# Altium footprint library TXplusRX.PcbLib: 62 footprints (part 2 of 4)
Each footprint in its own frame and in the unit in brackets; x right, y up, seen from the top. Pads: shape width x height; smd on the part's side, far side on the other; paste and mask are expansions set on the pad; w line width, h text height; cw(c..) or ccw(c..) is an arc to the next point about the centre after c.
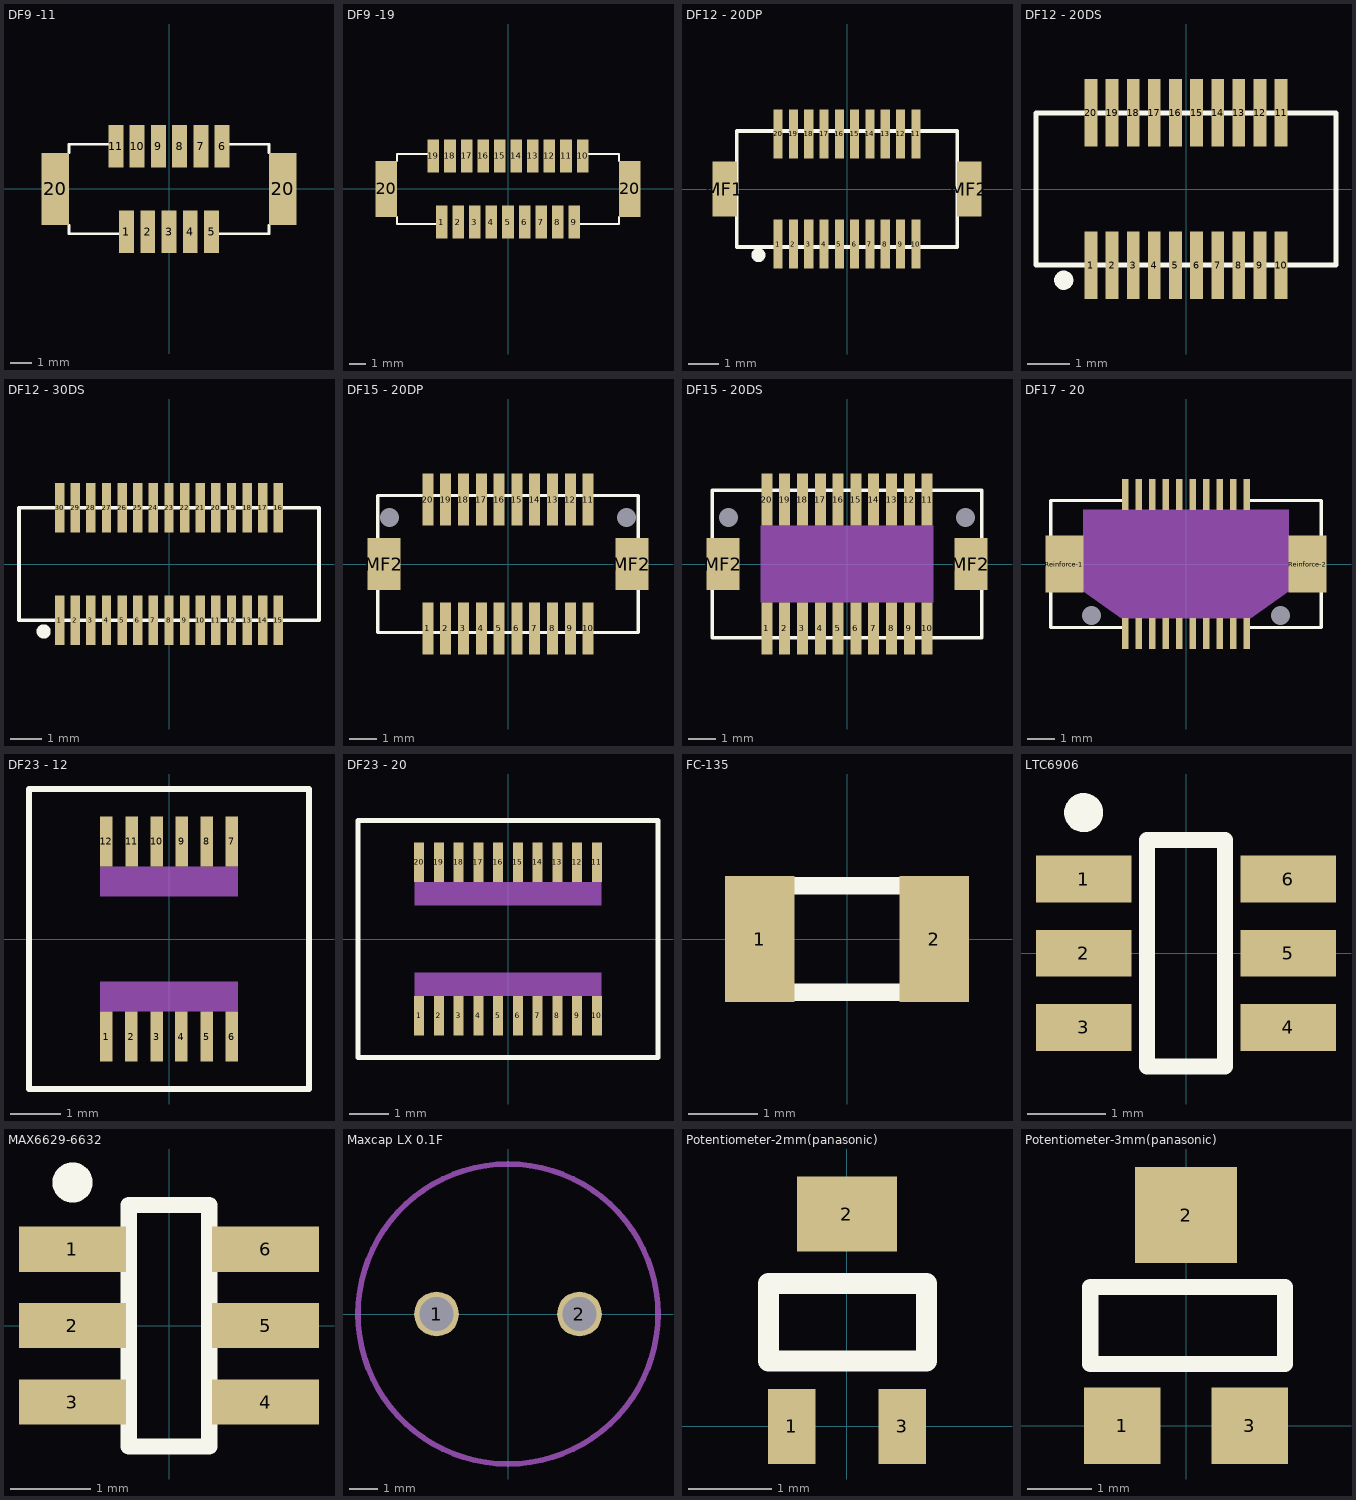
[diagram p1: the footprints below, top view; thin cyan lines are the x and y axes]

## DF9 -11 [mm] "DF9 -11, 11Pin Connector"
pads (13):
  rect 0.7x2 smd: 1(-2,-2) 2(-1,-2) 3(0,-2) 4(1,-2) 5(2,-2) 6(2.5,2) 7(1.5,2) 8(0.5,2) 9(-0.5,2) 10(-1.5,2) 11(-2.5,2)
  rect 1.3x3.4 smd: 20(-5.35,0) 20(5.35,0)
Top Overlay:
  lines w0.127: -4.7,-1.7 -4.7,-2.1 -2.3,-2.1 ; -4.7,1.7 -4.7,2.1 -2.8,2.1 ; 2.3,-2.1 4.7,-2.1 4.7,-1.7 ; 2.8,2.1 4.7,2.1 4.7,1.7

## DF9 -19 [mm] "DF9 -19, 19 Pin Connector"
pads (21):
  rect 0.7x2 smd: 1(-4,-2) 2(-3,-2) 3(-2,-2) 4(-1,-2) 5(0,-2) 6(1,-2) 7(2,-2) 8(3,-2) 9(4,-2) 10(4.5,2) 11(3.5,2) 12(2.5,2) 13(1.5,2) 14(0.5,2) 15(-0.5,2) 16(-1.5,2) 17(-2.5,2) 18(-3.5,2) 19(-4.5,2)
  rect 1.3x3.4 smd: 20(-7.35,0) 20(7.35,0)
Top Overlay:
  lines w0.127: -6.7,-1.7 -6.7,-2.1 -4.3,-2.1 ; -6.7,1.7 -6.7,2.1 -4.8,2.1 ; 4.3,-2.1 6.7,-2.1 6.7,-1.7 ; 4.8,2.1 6.7,2.1 6.7,1.7

## DF12 - 20DP [mm] "DF12 - 20DP, Connector Header"
height 2.3
pads (22):
  rect 0.3x1.6 smd: 1(-2.25,-1.8) 2(-1.75,-1.8) 3(-1.25,-1.8) 4(-0.75,-1.8) 5(-0.25,-1.8) 6(0.25,-1.8) 7(0.75,-1.8) 8(1.25,-1.8) 9(1.75,-1.8) 10(2.25,-1.8) 11(2.25,1.8) 12(1.75,1.8) 13(1.25,1.8) 14(0.75,1.8) 15(0.25,1.8) 16(-0.25,1.8) 17(-0.75,1.8) 18(-1.25,1.8) 19(-1.75,1.8) 20(-2.25,1.8)
  rect 0.8x1.8 smd: MF1(-4,0) MF2(4,0)
Top Overlay:
  circle w0.254: c-2.894,-2.159 r0.1
  lines w0.127: -3.6,-1.9 3.6,-1.9 3.6,1.9 -3.6,1.9 -3.6,-1.9
Mechanical 1:
  text "Conductors in area must be masked" at -2.1,0 h0.3
3D body: height 0, standoff 0, extent -2.4,-1 2.4,1

## DF12 - 20DS [mm] "DF12 - 20DS, Connector Receptacle"
height 2.7
pads (20):
  rect 0.3x1.6 smd: 1(-2.25,-1.8) 2(-1.75,-1.8) 3(-1.25,-1.8) 4(-0.75,-1.8) 5(-0.25,-1.8) 6(0.25,-1.8) 7(0.75,-1.8) 8(1.25,-1.8) 9(1.75,-1.8) 10(2.25,-1.8) 11(2.25,1.8) 12(1.75,1.8) 13(1.25,1.8) 14(0.75,1.8) 15(0.25,1.8) 16(-0.25,1.8) 17(-0.75,1.8) 18(-1.25,1.8) 19(-1.75,1.8) 20(-2.25,1.8)
Top Overlay:
  circle w0.254: c-2.894,-2.159 r0.1
  lines w0.127: -3.55,-1.8 3.55,-1.8 3.55,1.8 -3.55,1.8 -3.55,-1.8
Mechanical 1:
  text "Conductors in area must be masked" at -2.1,0 h0.3
3D body: height 0, standoff 0, extent -2.4,-1 2.4,1

## DF12 - 30DS [mm] "DF12 - 30DS, Connector Receptacle"
height 2.7
pads (30):
  rect 0.3x1.6 smd: 1(-3.5,-1.8) 2(-3,-1.8) 3(-2.5,-1.8) 4(-2,-1.8) 5(-1.5,-1.8) 6(-1,-1.8) 7(-0.5,-1.8) 8(0,-1.8) 9(0.5,-1.8) 10(1,-1.8) 11(1.5,-1.8) 12(2,-1.8) 13(2.5,-1.8) 14(3,-1.8) 15(3.5,-1.8) 16(3.5,1.8) 17(3,1.8) 18(2.5,1.8) 19(2,1.8) 20(1.5,1.8) 21(1,1.8) 22(0.5,1.8) 23(0,1.8) 24(-0.5,1.8) 25(-1,1.8) 26(-1.5,1.8) 27(-2,1.8) 28(-2.5,1.8) 29(-3,1.8) 30(-3.5,1.8)
Top Overlay:
  circle w0.254: c-4.012,-2.159 r0.1
  lines w0.127: -4.8,-1.8 4.8,-1.8 4.8,1.8 -4.8,1.8 -4.8,-1.8
Mechanical 1:
  text "Conductors in area must be masked" at -2.1,0 h0.3
3D body: height 0, standoff 0, extent -3.7,-1 3.7,1

## DF15 - 20DP [mm] "DF15 - 20DP, Connector Header"
height 3.2
pads (24):
  rect 0.4x1.9 smd: 1(-2.925,-2.35) 2(-2.275,-2.35) 3(-1.625,-2.35) 4(-0.975,-2.35) 5(-0.325,-2.35) 6(0.325,-2.35) 7(0.975,-2.35) 8(1.625,-2.35) 9(2.275,-2.35) 10(2.925,-2.35) 11(2.925,2.35) 12(2.275,2.35) 13(1.625,2.35) 14(0.975,2.35) 15(0.325,2.35) 16(-0.325,2.35) 17(-0.975,2.35) 18(-1.625,2.35) 19(-2.275,2.35) 20(-2.925,2.35)
  round 0 hole 0.7 unplated: 2(4.325,1.7) boss1(-4.325,1.7)
  rect 1.2x1.9 smd: MF2(-4.525,0) MF2(4.525,0)
Top Overlay:
  lines w0.127: -4.75,-2.5 4.75,-2.5 4.75,2.5 -4.75,2.5 -4.75,-2.5

## DF15 - 20DS [mm] "DF15 - 20DS, Connector Receptacle"
height 3.2
pads (24):
  rect 0.4x1.9 smd: 1(-2.925,-2.35) 2(-2.275,-2.35) 3(-1.625,-2.35) 4(-0.975,-2.35) 5(-0.325,-2.35) 6(0.325,-2.35) 7(0.975,-2.35) 8(1.625,-2.35) 9(2.275,-2.35) 10(2.925,-2.35) 11(2.925,2.35) 12(2.275,2.35) 13(1.625,2.35) 14(0.975,2.35) 15(0.325,2.35) 16(-0.325,2.35) 17(-0.975,2.35) 18(-1.625,2.35) 19(-2.275,2.35) 20(-2.925,2.35)
  round 0 hole 0.7 unplated: boss1(-4.325,1.7) boss2(4.325,1.7)
  rect 1.2x1.9 smd: MF2(-4.525,0) MF2(4.525,0)
Top Overlay:
  lines w0.127: -4.925,-2.7 4.925,-2.7 4.925,2.7 -4.925,2.7 -4.925,-2.7
Mechanical 1:
  rectangle: -3.163,-1.4 3.163,1.4
  text "Conductors in area must be masked" at -2.8,-1.9 h0.4

## DF17 - 20 [mm] "DF17 - 20, Connector"
pads (24):
  rect 0.25x1.15 smd: 1(-2.25,-2.575) 2(-1.75,-2.575) 3(-1.25,-2.575) 4(-0.75,-2.575) 5(-0.25,-2.575) 6(0.25,-2.575) 7(0.75,-2.575) 8(1.25,-2.575) 9(1.75,-2.575) 10(2.25,-2.575) 11(2.25,2.575) 12(1.75,2.575) 13(1.25,2.575) 14(0.75,2.575) 15(0.25,2.575) 16(-0.25,2.575) 17(-0.75,2.575) 18(-1.25,2.575) 19(-1.75,2.575) 20(-2.25,2.575)
  round 0 hole 0.7 unplated: Guide_Post-1(-3.5,-1.9) Guide_Post-2(3.5,-1.9)
  rect 1.4x2.1 smd: Reinforce-1(-4.5,0) Reinforce-2(4.5,0)
Top Overlay:
  lines w0.127: -5,-1.05 -5,-2.35 -2.35,-2.35 ; -5,1.05 -5,2.35 -2.35,2.35 ; 2.35,-2.35 5,-2.35 5,-1.05 ; 2.4,2.35 5,2.35 5,1.05
Mechanical 1:
  region: -3.8,2 -3.8,-1 -2.4,-2 2.4,-2 3.8,-1 3.8,2
  text "Conductors in area must be masked" at -1.4,-2.3 h0.2

## DF23 - 12 [mm] "DF23 - 12, Connector"
height 1.2
pads (12):
  rect 0.25x1 smd: 1(-1.25,-1.95) 2(-0.75,-1.95) 3(-0.25,-1.95) 4(0.25,-1.95) 5(0.75,-1.95) 6(1.25,-1.95) 7(1.25,1.95) 8(0.75,1.95) 9(0.25,1.95) 10(-0.25,1.95) 11(-0.75,1.95) 12(-1.25,1.95)
Top Overlay:
  lines w0.127: -2.8,-3 2.8,-3 2.8,3 -2.8,3 -2.8,-3
Mechanical 1:
  rectangle: -1.375,-1.45 1.375,-0.85
  rectangle: -1.375,0.85 1.375,1.45
  text "Conductors in area must be masked" at -1.375,-0.7 h0.2

## DF23 - 20 [mm] "DF23 - 20, Connector"
height 1.2
pads (20):
  rect 0.25x1 smd: 1(-2.25,-1.95) 2(-1.75,-1.95) 3(-1.25,-1.95) 4(-0.75,-1.95) 5(-0.25,-1.95) 6(0.25,-1.95) 7(0.75,-1.95) 8(1.25,-1.95) 9(1.75,-1.95) 10(2.25,-1.95) 11(2.25,1.95) 12(1.75,1.95) 13(1.25,1.95) 14(0.75,1.95) 15(0.25,1.95) 16(-0.25,1.95) 17(-0.75,1.95) 18(-1.25,1.95) 19(-1.75,1.95) 20(-2.25,1.95)
Top Overlay:
  lines w0.127: -3.8,-3 3.8,-3 3.8,3 -3.8,3 -3.8,-3
Mechanical 1:
  rectangle: -2.375,-1.45 2.375,-0.85
  rectangle: -2.375,0.85 2.375,1.45
  text "Conductors in area must be masked" at -2.375,-0.7 h0.2

## FC-135 [mm] "FC-135   crystal - epson eletronics"
height 0.8
pads (2):
  rect 1x1.8 smd: 1(-1.25,0) 2(1.25,0)
Top Overlay:
  lines w0.254: -0.762,-0.762 0.762,-0.762 ; -0.762,0.762 0.762,0.762

## LTC6906 [mm] "SOT23, 6-Leads, Body 2.90x2.80mm, Pitch 0.95mm, IPC Medium Density"
height 1
pads (6):
  rect 1.22x0.6 smd: 1(-1.31,0.95) 2(-1.31,0) 3(-1.31,-0.95) 4(1.31,-0.95) 5(1.31,0) 6(1.31,0.95)
Top Overlay:
  circle w0.25: c-1.31,1.8 r0.125
  lines w0.2: -0.5,-1.45 0.5,-1.45 0.5,1.45 -0.5,1.45 -0.5,-1.45
3D body: height 1, standoff 0.01, extent -0.875,-1.45 0.875,1.45

## MAX6629-6632 [mm] "SOT23, 6-Leads, Body 2.90x2.80mm, Pitch 0.95mm, IPC Medium Density"
height 1.45
pads (6):
  rect 1.33x0.56 smd: 1(-1.2,0.95) 2(-1.2,0) 3(-1.2,-0.95) 4(1.2,-0.95) 5(1.2,0) 6(1.2,0.95)
Top Overlay:
  circle w0.25: c-1.2,1.78 r0.125
  lines w0.2: -0.5,-1.5 0.5,-1.5 0.5,1.5 -0.5,1.5 -0.5,-1.5
3D body: height 1.45, standoff 0, extent -0.875,-1.5 0.875,1.5

## Maxcap LX 0.1F [mm] "Maxcap LX Series, 0.1F, Diameter  11mm, Leads 5.1mm"
height 6.5
pads (2):
  round 1.6 hole 1.2: 1(-2.55,0) 2(2.55,0)
Mechanical 1:
  circle w0.2: c0,0 r5.35

## Potentiometer-2mm(panasonic) [mm]
pads (3):
  rect 0.575x0.9 smd: 1(-0.663,0) 3(0.663,0)
  rect 1.2x0.9 smd: 2(0,2.55)
Top Overlay:
  lines w0.254: -0.94,0.787 0.953,0.787 0.953,1.714 -0.94,1.714 -0.94,0.787

## Potentiometer-3mm(panasonic) [mm]
pads (3):
  rect 1.2x1.2 smd: 1(-1,0) 3(1,0)
  rect 1.6x1.5 smd: 2(0,3.3)
Top Overlay:
  lines w0.254: -1.499,0.965 1.549,0.965 1.549,2.172 -1.499,2.172 -1.499,0.965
